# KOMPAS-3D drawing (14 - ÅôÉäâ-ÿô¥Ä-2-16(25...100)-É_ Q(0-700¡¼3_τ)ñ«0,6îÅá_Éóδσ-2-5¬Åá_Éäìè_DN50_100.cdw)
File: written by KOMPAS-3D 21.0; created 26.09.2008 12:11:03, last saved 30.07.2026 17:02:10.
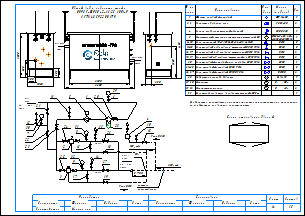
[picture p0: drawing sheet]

Sheets 1-2: A3, landscape

Document properties: Наименование: Макро:21; Автор: RaskoAdmin; Форматы листов документа: 2xA3; Полное имя файла: \\UR38nt01\Departments\КТО\КБ ПУРДГ\Заявки\Прайс-лист на типовые шкафы ГРПШ\ПУРДГ_стандарт_30_04_2026\ПУРДГ с РДНК\ПУРДГ-ШУЭО-2-16(25...100)-Р_ Q(0-700нм3_ч)до0,6МПа_Рвых-2-5кПа_РДНК_DN50_100.cdw

Title block, sheet 1: Наименование: Пункт учета газа / ПУГ-Ш-400-Р / ЛГТИ.485922.001ТУ; designation: ЛГТИ.03.4411141; sheet number: 1; Количество листов документа: 2; organisation: ООО "ЭЛЬСТЕР Газэлектроника"; Форматы листов документа: A3; stored path: C:\Рабочие документы\Компас\ПУГ\Схема.cdw; Разработал: Устинов; Проверил: Кошкин; Утвердил: Кошкин
Title block, sheet 2: sheet number: 2; stored path: D:\Рабочие документы\Заявки\ПУРДГ\ПУРДГ-ШУЭО-2-100-Р 4411220.cdw; designation, second copy: ЛГТИ.03.4411141-

Views: Вид 1, Вид 2
Referenced files: wcvoit.frw
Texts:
  Normal
  № на
  схеме
  Усл.
  обозн.
  Марка
  (модель)
  Кол.
  Фильтр газовый фланцевый
  ФГ 16-50
  Регулятор давления газа
  РДНК-50
  Клапан предохранительный сбросной
  КПС DN20
  Измерительный комплекс с ротационным счетчиком Ду50
  СГ-ЭК-Р-(0,2...2,0)-
  Кран кнопочный VE-РАСКО-НЗ-1,6-G1/2-М20
  DN15
  Кран шаровой "под приварку" штуцерный DN20 PN16
  DN20
  Кран шаровой "под приварку" штуцерный DN15 PN16
  Кран шаровой "под приварку" штуцерный п/п DN15 PN16
  Кран шаровой фланцевый с мех. приводом DN50 PN16
  Кран шаровой фланцевый DN50 PN16
  Кран шаровой фланцевый DN100 PN16
  DN50
  DN100
  Индикатор перепада давления
  Манометр
  Манометр-напоромер
  Электрообогреватель взрывозащищенный 400Вт
  Delta 15
  0...     МПа
  0...     кПа
  Общий вид и габариты шкафа
  ПУРДГ-ШУЭО-2-16(25...100)-Р
  Выход газа
  Вход газа
  logo-rasko-ge.png
  DN 1
  местное
  сопротивление
  Римп DN15
  Римп DN20
  Выход
  газа
  Р=     кПа
  Вход
  Р=       МПа
  PDI
  Схема открывания дверей
  Предприятие изготовитель может заменять комплектующие на аналогичные,
  не ухудшающие заявленных характеристик.
  Должность
  Конструктор
  Фамилия
  Подпись
  Дата
  Согласовано
  Максимкин
  Лист
  Листов
  POLYLINE_STYLE_0.18_RGB_0_0_0
  POLYLINE_STYLE_0.50_RGB_0_0_0
  POLYLINE_STYLE_0.34_RGB_0_0_0
  PHANTOM_RGB_0_0_0_SC_1_THICK_0.18
  K5LT_THIN_RGB_0_0_0_THICK_0.18
  K5LT32769_RGB_0_0_0_THICK_0.18
  K5LT12_RGB_0_0_0_SC_1_THICK_0.18
  K5LT_DASHED_RGB_0_0_0_SC_1_THICK_0.18
  ACISOTGL_RGB_0_0_0_SC_0.8_THICK_0.25
  CONTINUOUS_RGB_0_127_31_THICK_0.3
  CONTINUOUS_RGB_0_0_255_THICK_0.35
  CONTINUOUS_RGB_255_0_0_THICK_0.35
  POLYLINE_STYLE_0.25_RGB_0_0_0
  CONTINUOUS_RGB_0_0_0_THICK_0.5
  POLYLINE_STYLE_0.35_RGB_0_0_255
  CONTINUOUS_RGB_0_0_0_THICK_0.4
  CONTINUOUS_RGB_0_0_0_THICK_0.35
  НЕВИДИМАЯ_RGB_0_0_0_SC_0.3_THICK_0.25
  СONTINUOUS_RGB_0_0_0_THICK_0.25
  ОСЕВАЯ2_RGB_248_153_30_SC_0.3_THICK_0.25
  Без оформления
Dimensions and other numbers on the sheet: 1; 2, 3; 2; 4; 5; 6-10; 11-15; 16, 17; 18, 19; 20; 21-25; 26, 27; 28; 29, 30; 31, 32; 33; 1500; 250; 300; 1050; 550; 305; 2300; 4130; 2000; 2600; 5,,,7DN 1; 7; 30; 12; 21; 22; 23; 11; 6; 29; 24; 31; 8; 16; 13; 26; 18; 10; 15; 25; 32; 9; 3; 17; 14; 27; 19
